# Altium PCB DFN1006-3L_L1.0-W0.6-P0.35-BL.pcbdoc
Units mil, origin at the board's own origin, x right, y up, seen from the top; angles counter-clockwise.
Board outline 570 x 570 mil, 2 copper layers (Top Layer, Bottom Layer), stack 0 mil thick; 1 components, 0 nets, 3 pads, 0 vias.
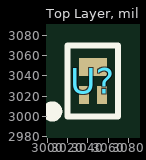
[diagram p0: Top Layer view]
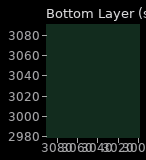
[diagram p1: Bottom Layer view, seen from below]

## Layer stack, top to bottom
Top Layer: signal copper (thickness not stored)
Bottom Layer: signal copper (thickness not stored)

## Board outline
3320,2750 2750,2750 2750,3320 3320,3320

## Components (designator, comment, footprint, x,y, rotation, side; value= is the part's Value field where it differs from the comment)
U? "" DFN1006-3L_L1.0-W0.6-P0.35-BL 3045,3035.02 r0 top

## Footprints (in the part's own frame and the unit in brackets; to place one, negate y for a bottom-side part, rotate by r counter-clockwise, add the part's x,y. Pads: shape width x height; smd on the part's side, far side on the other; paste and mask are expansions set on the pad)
DFN1006-3L_L1.0-W0.6-P0.35-BL [mm]
  rect 0.25x0.45 smd: 1(-0.225,-0.35) 2(0.225,-0.35)
  rect 0.7x0.45 smd: 3(0,0.35)
  silkscreen extent -1.14,-0.89 0.64,0.89

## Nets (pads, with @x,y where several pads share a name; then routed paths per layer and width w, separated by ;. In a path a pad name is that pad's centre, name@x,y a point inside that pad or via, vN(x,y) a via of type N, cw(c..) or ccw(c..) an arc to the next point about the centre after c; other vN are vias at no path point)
pads on no net: U?.1 U?.2 U?.3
